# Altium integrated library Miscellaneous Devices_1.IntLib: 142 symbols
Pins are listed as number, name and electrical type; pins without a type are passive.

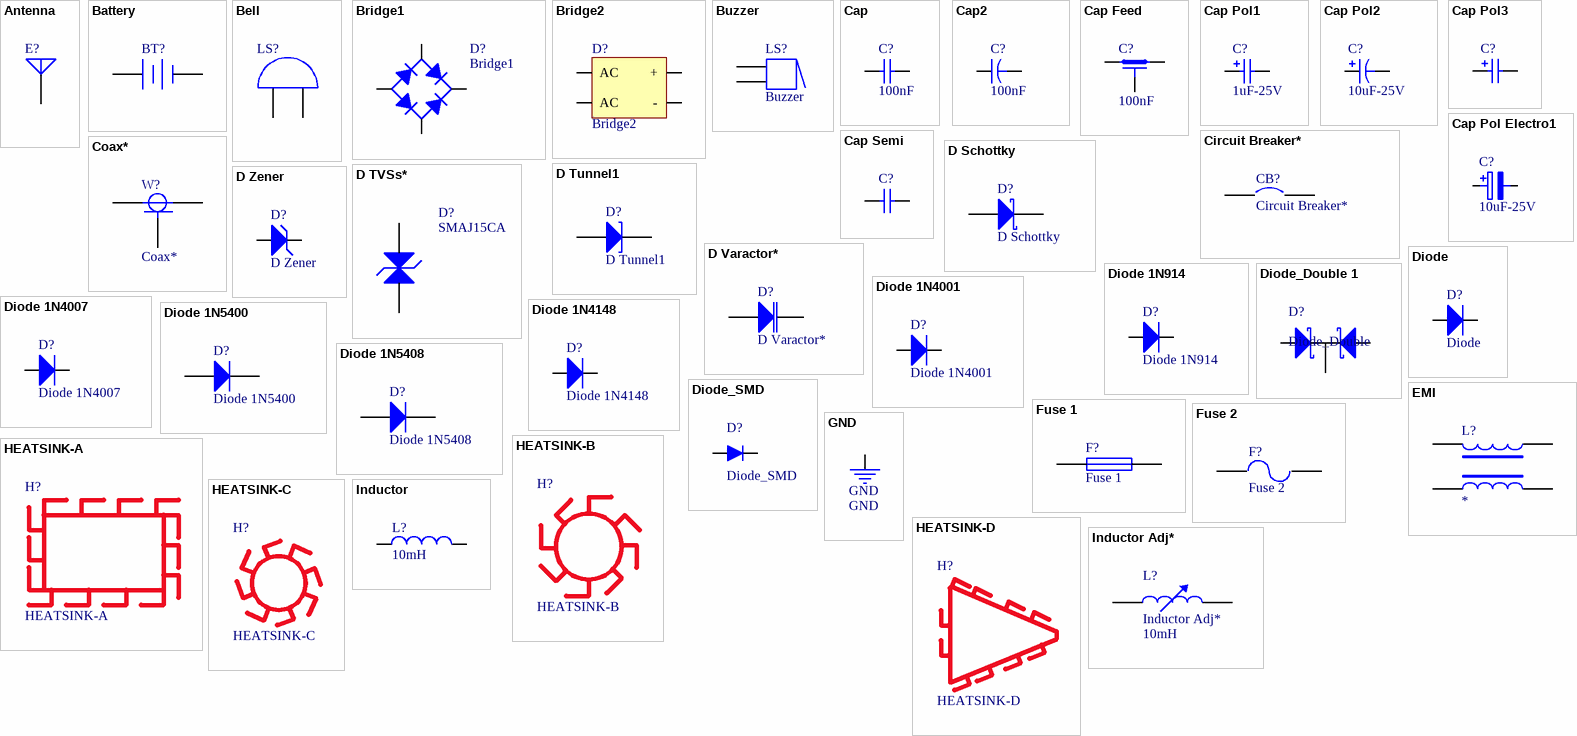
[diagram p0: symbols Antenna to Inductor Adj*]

## Antenna
designator E?
Generic Antenna
footprint PIN1 (Connector; Coax-F)
pins: 1 A

## Battery
designator BT?
Multicell Battery
footprint BAT-2 (Multicell Battery; 2 Leads)
footprint MT6CON2V
footprint MKDS3_2RMI
pins: 1 +, 2 -

## Bell
designator LS?
Electrical Bell
footprint PIN2 (Electrical Bell; 2 Leads)
pins: 1 A, 2 B

## Bridge1
designator D?
Full Wave Diode Bridge
footprint E-BIP-P4/D10 (Bridge Rectifier; 4 Terminals; Body 9.4 x 9.4 mm (typ); Pitch 5.08 mm)
simulation model BRIDGE (Spice Subcircuit)
footprint BRIDGE-1 (created by: M.Hariri (designer))
footprint BRIDGE-2
footprint BRIDGE-3
footprint BRIDGE-4
footprint BRIDGE-5
footprint BRIDGE-6
footprint BRIDGE-7
pins: 1 A, 2 C, 3 K, 4 C

## Bridge2
designator D?
Diode Bridge
footprint E-BIP-P4/X2.1 (Bridge Rectifier; 4 Terminals; Body 16.8 x 16.8 mm (typ); Pitch 10.67 mm)
simulation model BRIDGE (Spice Subcircuit)
footprint BRIDGE-1
footprint BRIDGE-2
footprint BRIDGE-3
footprint BRIDGE-4
footprint BRIDGE-5
footprint BRIDGE-6
footprint BRIDGE-7
pins: 1 -, 2 AC, 3 +, 4 AC

## Buzzer
designator LS?
Magnetic Transducer Buzzer; Revision 1: Jul-2002: Re-released for DXP Platform.; Revision 2: 17-Dec-2003: Schematic revised, PCB Footprint replaced.
footprint ABSM-1574 (Magnetic Transducer Buzzer)
footprint BUZZER
pins: 1, 1A, 2, 2A
1 alternate drawing of the same symbol

## Cap
designator C?, comment 100nF
Capacitor; Value: 100pF
footprint RAD-0.3 (Capacitor; 2 Leads)
simulation model CAP (Capacitor)
signal-integrity model Cap
footprint CAPR5.08-7.8X3.2
footprint CAPR2.54-5.1X3.2
footprint RAD0.1
footprint RAD0.15
footprint RAD0.2
footprint RAD0.2II
footprint RAD0.2III
footprint RAD0.3
footprint RAD0.3II
footprint RAD0.4
footprint RAD0.4II
footprint RAD0.6
footprint RAD0.6II
footprint RAD1.25
pins: 1, 2

## Cap2
designator C?, comment 100nF
Capacitor; Value: 100pF
footprint CAPR5-4X5 (Capacitor; 2 Leads)
simulation model CAP (Capacitor)
signal-integrity model Cap
footprint RAD0.1
footprint RAD0.2
footprint RAD0.2II
pins: 1, 2

## Cap Feed
designator C?, comment 100nF
Feed-Through Capacitor; Note: Commonly used for bypassing high-frequency currents to chassis; Value: 100pF
footprint SIP3
signal-integrity model Cap Feed
pins: 1, 2, 3

## Cap Pol1
designator C?, comment 1uF-25V
Polarized Capacitor (Radial); Value: 100pF
footprint RB7.6-15
simulation model CAP (Capacitor)
signal-integrity model Cap Pol
footprint CAPPR1.5-4X5
footprint CAPPR1.27-1.96X4.06
footprint CAPPR2-5X6.8
footprint CAPPR5-5X5
footprint CAPPR7.5-16X35
footprint RB.1/.2
footprint RB.2/.3
footprint RB.2/.3II
footprint RB.2/.4
footprint RB.3/.6
footprint RB.3/.64
footprint RB.4/.8
footprint RB.4/1.0
footprint RB.47/1.0
footprint RB.47/1.2
footprint RB.5/1.0
footprint RB1.4/.4
footprint RB1.6/.9
footprint RB.3/.6HI
footprint RB.3/.6HII
pins: 1, 2

## Cap Pol2
designator C?, comment 10uF-25V
Polarized Capacitor (Axial); Value: 100pF
footprint POLAR0.8 (Polarized Capacitor (Axial); 2 Leads)
simulation model CAP (Capacitor)
signal-integrity model Cap Pol
footprint CAPPA14.05-10.5x6.3
footprint CAPPA23.6-18.5x8.5
footprint CAPPA31.6-26.5x12.5
footprint CAPPA35.6-30.5x18.5
footprint CAPPA46.1-41x21.5
footprint RB3/6
footprint RB5/10
pins: 1, 2

## Cap Pol3
designator C?, comment 1uF-10V  (value not drawn)
Polarized Capacitor (Surface Mount)
footprint CC2012-0805 (Chip Capacitor; Body 2.0 x 1.2 mm (LxW typ))
simulation model CAP (Capacitor)
signal-integrity model Cap Pol
footprint CC4532-1812
footprint CC4564-1825
footprint CC5750-2220
footprint CC5664-2225
footprint CC3216-1206
footprint CC3225-1210
pins: 1, 2

## Cap Pol Electro1
designator C?, comment 10uF-25V
Polarized Capacitor (Radial); Value: 100pF
footprint RB7.6-15 (Polarized Capacitor (Radial); 2 Leads)
simulation model CAP (Capacitor)
signal-integrity model Cap Pol
footprint CAPPR1.5-4X5
footprint CAPPR1.27-1.96X4.06
footprint CAPPR2-5X6.8
footprint CAPPR5-5X5
footprint CAPPR7.5-16X35
footprint RB.1/.2
footprint RB.2/.3
footprint RB.2/.3II
footprint RB.2/.4
footprint RB.3/.6
footprint RB.3/.64
footprint RB.4/.8
footprint RB.4/1.0
footprint RB.47/1.0
footprint RB.47/1.2
footprint RB.5/1.0
footprint RB1.4/.4
footprint RB1.6/.9
footprint RB.3/.6HI
footprint RB.3/.6HII
footprint RB.2/.8
pins: 1, 2

## Cap Semi
designator C?, comment 100nF  (value not drawn)
Capacitor (Semiconductor SIM Model)
footprint CC3216-1206 (Chip Capacitor; Body 3.2 x 1.6 mm (LxW typ))
simulation model CAP (Semiconductor Capacitor)
signal-integrity model Cap Semi
footprint CC1310-0504
footprint CC1608-0603
footprint CC1005-0402
footprint CC3225-1210
pins: 1, 2

## Circuit Breaker*
designator CB?
Circuit Breaker
footprint SPST-2 (Circuit Breaker; 2 Leads)
pins: 1, 2

## Coax*
designator W?
Coaxial
pins: 1 CENTER 1, 2 CENTER 2, 3 SHIELD

## D Schottky
designator D?
Schottky Diode; Code - JEDEC: DO-214-AA
footprint DSO-C2/X2.3 (DO-214-AA/SMB; 2 C-Bend Leads; Body 5.3 x 3.6 mm, inc. leads (LxW))
simulation model SKYDIODE (Diode)
signal-integrity model D Schottky
footprint DIODE0.4
pins: 1 A, 2 K

## D Tunnel1
designator D?
Tunnel Diode - RLC Model; Revision 1: 15-Apr-2002: Text note added.; Revision 2: July-2002: Re-released for DXP Platform.
footprint DSO-F2/D6.1 (SMT LED; 2 Flat Leads)
simulation model DTUNNEL1 (Spice Subcircuit)
signal-integrity model D Tunnel
footprint DIODE0.4III
pins: 1 A, 2 K

## D TVSs*
designator D?, comment SMAJ15CA
400W SURFACE MOUNT TRANSIENT VOLTAGE  SUPPRESSOR
footprint SMA (Footprint not found)
pins: 1 A1, 2 A2

## D Varactor*
designator D?
Variable Capacitance Diode; Note: Pin 2 is not connected and not drawn; Code - JEDEC: SOT23
footprint SO-G3/Z3.3 (SOT-23; 3 Leads; Body 3.0 x 2.5 mm, inc. leads (LxW max))
simulation model BBY31 (Diode)
signal-integrity model D Varactor
pins: 1 K, 3 A

## D Zener
designator D?
Zener Diode
footprint DIODE-0.7 (Zener Diode; 2 Leads)
simulation model ZENER (Diode)
signal-integrity model D Zener
footprint DIODE0.4
footprint DIODE0.4II
footprint DIODE0.4II
footprint DIODE0.4IV
footprint DIODE0.45
footprint DIODE0.5
footprint DIODE0.5II
footprint DIODE0.6
footprint DIODE0.7
pins: A, K
1 alternate drawing of the same symbol

## Diode
designator D?
Default Diode; Code - JEDEC: DO-214-AB
footprint DSO-C2/X3.3 (DO-214-AB/SMC; 2 C-Bend Leads; Body 7.9 x 5.9 mm, inc. leads (LxW))
simulation model DIODE (Diode)
signal-integrity model Diode
footprint DIODE0.2
footprint DIODE0.2II
footprint DIODE0.3
footprint DIODE0.35
footprint DIODE0.4
footprint DIODE0.4III
footprint DIODE0.4II
footprint DIODE0.4IV
footprint DIODE0.5
footprint DIODE0.5II
footprint DIODE0.6
footprint DIODE0.7
footprint DIODE0.8
footprint DIODE0.8II
footprint DIODE0.7V
pins: A, K

## Diode 1N914
designator D?
High Conductance Fast Diode; Revision 1: 11-Jul-2000: SIM Model Added.; Revision 2: 17-Jul-2002: Re-released for DXP Platform.; Code - JEDEC: DO-204-AH
footprint DIO7.1-3.9x1.9 (Diode, Axial; Body 3.8 x 1.9 mm (LxDia. max), Lead Dia. 0.53 mm (max))
simulation model 1N914 (DIODE)
signal-integrity model 1N914
footprint DIODE0.2
footprint DIODE0.2II
footprint DIODE0.3
footprint DIODE0.35
footprint DIODE0.4
footprint DIODE0.4II
footprint DIODE0.4III
footprint DIODE0.4IV
pins: 1 A, 2 K

## Diode 1N4001
designator D?
1 Amp General Purpose Rectifier; Revision 1: 11-Jul-2000: SIM Model Added.; Revision 2: 17-Jul-2002: Re-released for DXP Platform.; Package Information: Latest Revision: Aug-1999; Code - JEDEC: DO-204-AL
footprint DIO10.46-5.3x2.8 (Diode, Axial; Body 5.2 x 2.7 mm (LxDia. max), Lead Dia. 0.86 mm (max))
simulation model 1N4001 (DIODE)
signal-integrity model 1N4001
footprint DIODE0.4
footprint DIODE0.4II
footprint DIODE0.4III
footprint DIODE0.4IV
footprint DIODE0.45
footprint DIODE0.5
footprint DIODE0.5II
footprint DIODE0.6
pins: 1 A, 2 K

## Diode 1N4007
designator D?
1 Amp General Purpose Rectifier; Revision 1: 11-Jul-2000: SIM Model Added.; Revision 2: 17-Jul-2002: Re-released for DXP Platform.; Package Information: Latest Revision: Aug-1999; Code - JEDEC: DO-204-AL
footprint DIO10.46-5.3x2.8 (Diode, Axial; Body 5.2 x 2.7 mm (LxDia. max), Lead Dia. 0.86 mm (max))
simulation model 1N4007 (DIODE)
signal-integrity model 1N4007
footprint DIODE0.4
footprint DIODE0.4II
footprint DIODE0.4III
footprint DIODE0.4IV
footprint DIODE0.5
footprint DIODE0.5II
footprint DIODE0.6
footprint DIODE0.45
pins: 1 A, 2 K

## Diode 1N4148
designator D?
High Conductance Fast Diode; Revision 1: 11-Jul-2000: SIM Model Added.; Revision 2: 17-Jul-2002: Re-released for DXP Platform.; Code - JEDEC: DO-204-AH
footprint DIO7.1-3.9x1.9 (Diode, Axial; Body 3.8 x 1.9 mm (LxDia. max), Lead Dia. 0.53 mm (max))
simulation model 1N4148 (DIODE)
signal-integrity model 1N4148
footprint DIODE0.2
footprint DIODE0.2II
footprint DIODE0.3
footprint DIODE0.35
footprint DIODE0.4
footprint DIODE0.4II
footprint DIODE0.4III
footprint DIODE0.4IV
pins: 1 A, 2 K

## Diode 1N5400
designator D?
3 Amp General Purpose Rectifier; Revision 1: 11-Jul-2000: SIM Model Added.; Revision 2: 17-Jul-2002: Re-released for DXP Platform.; Package Information: Latest Revision: Aug-1999
footprint DIO18.84-9.6x5.6 (Diode, Axial; Body 9.5 x 5.6 mm (LxDia. max), Lead Dia. 1.32 mm (max))
simulation model 1N5400 (DIODE)
signal-integrity model 1N5400
footprint DIODE0.7
footprint DIODE0.8
footprint DIODE0.8II
footprint DIODE0.7V
pins: 1 A, 2 K

## Diode 1N5408
designator D?
3 Amp Medium Power Silicon Rectifier Diode; Revision 1: 10-Jul-2000: SIM Model Added.; Revision 2: 17-Jul-2002: Re-released for DXP Platform.
footprint DIO18.84-9.6x5.6 (Diode, Axial; Body 9.5 x 5.3 mm (LxDia. max), Lead Dia. 1.32 mm (max))
simulation model 1N5408 (DIODE)
signal-integrity model 1N5408
footprint DIODE0.7
footprint DIODE0.8
footprint DIODE0.8II
footprint DIODE0.7V
pins: 1 A, 2 K

## Diode_Double 1
designator D?, comment Diode_Double
footprint TO220V
footprint TO220H
pins: 1 A, 2 K, 3 A

## Diode_SMD
designator D?
Default Diode; Code - JEDEC: DO-214-AB
simulation model DIODE (Diode)
signal-integrity model Diode
footprint MELF-D3516-1406
footprint DO-214AC(SMA) (Footprint not found)
pins: 1 A, 2 K

## EMI
designator L?
footprint EMI-A
pins: 1, 2, 3, 4
2 alternate drawings of the same symbol

## Fuse 1
designator F?
Fuse
footprint PIN-W2/E2.8 (Fuse; 2 Leads)
simulation model FUSE (Spice Subcircuit)
footprint FUSE-I
footprint FUSE-II
footprint CR3216-1206
pins: 1, 1a, 2, 2a

## Fuse 2
designator F?
Fuse
footprint PIN-W2/E2.8 (Fuse; 2 Leads)
simulation model FUSE (Spice Subcircuit)
footprint FUSE-I
footprint FUSE-II
pins: 1, 1a, 2, 2a

## GND
designator GND
footprint PAD(OCTAGONAL) (- Library created by DESIGNER(M.Hariri))
pins: 1 (power)
2 alternate drawings of the same symbol

## HEATSINK-A
designator H?
HEAT SINK_created by designer(M.Hariri)
footprint HEATSINK-1
footprint HEATSINK-2
footprint HEATSINK-3
footprint HEATSINK-4
2 alternate drawings of the same symbol

## HEATSINK-B
designator H?
HEAT SINK_created by designer(M.Hariri)
footprint HEATSINK-1
footprint HEATSINK-2
footprint HEATSINK-3
footprint HEATSINK-4
2 alternate drawings of the same symbol

## HEATSINK-C
designator H?
HEAT SINK_created by designer(M.Hariri)
2 alternate drawings of the same symbol

## HEATSINK-D
designator H?
HEAT SINK_created by designer(M.Hariri)
2 alternate drawings of the same symbol

## Inductor
designator L?, comment 10mH
Inductor
footprint C1005-0402 (Inductor; 2 Leads)
simulation model INDUCTOR (Inductor)
signal-integrity model Inductor
footprint CC4532-1812
footprint AXIAL0.4
footprint AXIAL0.5
footprint AXIAL0.6
pins: 1, 2

## Inductor Adj*
designator L?  value 10mH
Adjustable Inductor; Set Position: 0.5
footprint AXIAL-0.8 (Adjustable Inductor; 2 Leads)
simulation model INDUCTOR (Inductor)
signal-integrity model Inductor Adj
pins: 1, 2

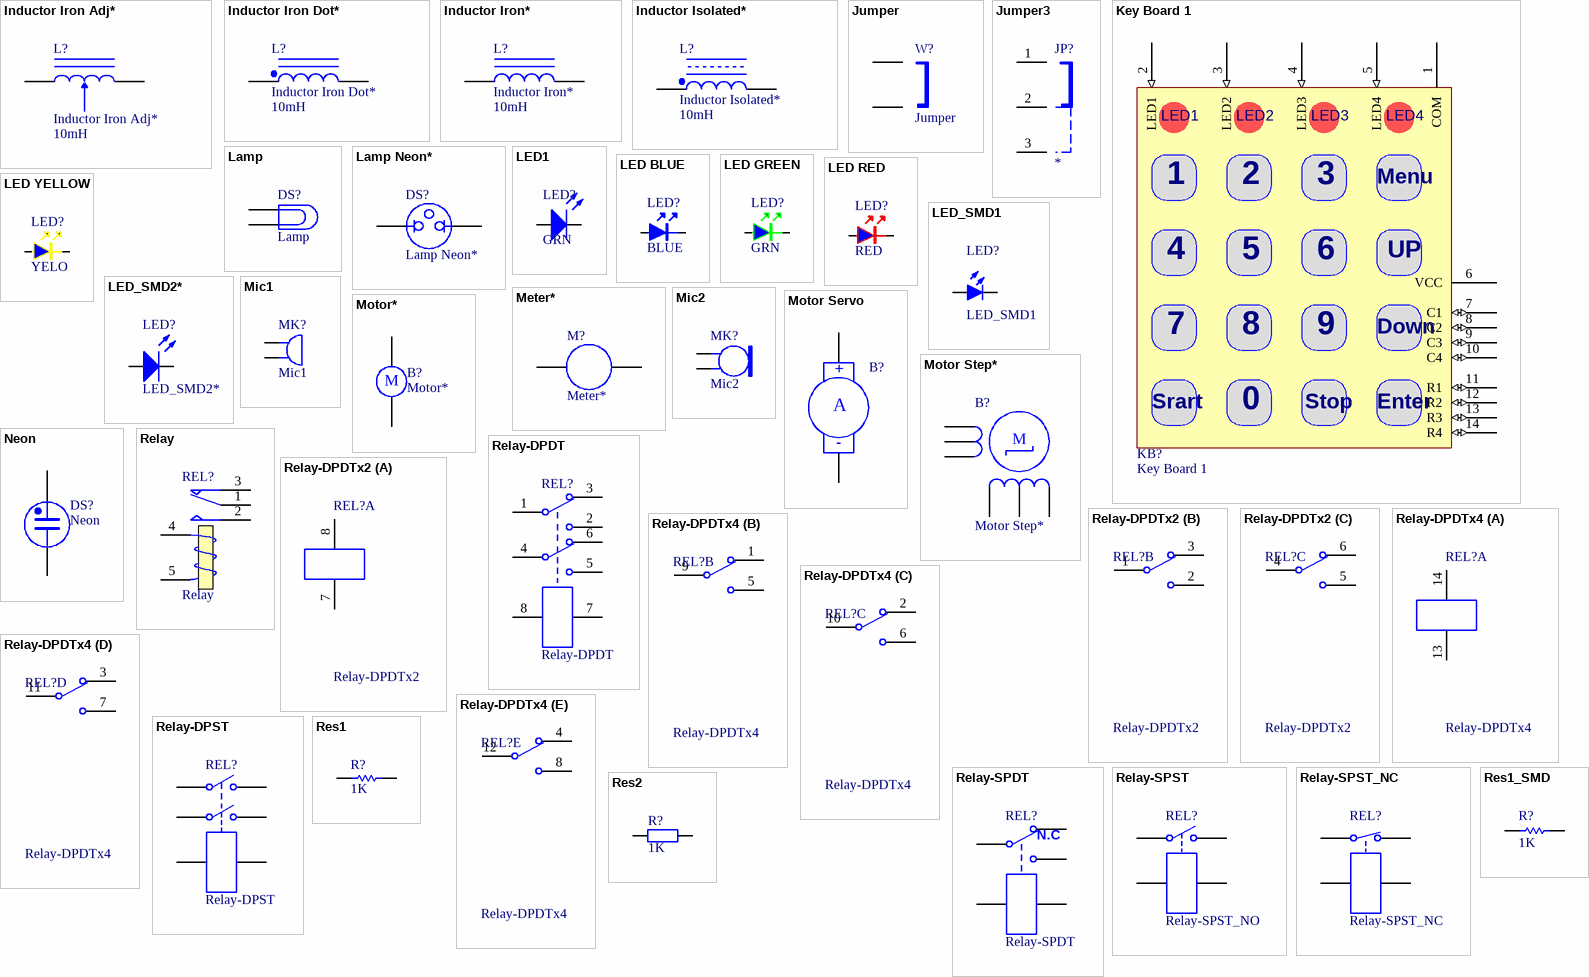
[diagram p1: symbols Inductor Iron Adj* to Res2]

## Inductor Iron Adj*
designator L?  value 10mH
Adjustable Magnetic-Core Inductor; Set Position: 0.5
footprint AXIAL-1.0 (Adjustable Magnetic-Core Inductor; 2 Leads)
simulation model INDUCTOR (Inductor)
signal-integrity model Inductor Iron Adj
pins: 1, 2

## Inductor Iron Dot*
designator L?  value 10mH
Magnetic-Core Inductor with Winding Polarity Marking
footprint DIODE SMC (Magnetic-Core Inductor with Winding Polarity Marking; 2 Leads)
signal-integrity model Inductor Iron Dot
pins: 1, 2

## Inductor Iron*
designator L?  value 10mH
Magnetic-Core Inductor
footprint AXIAL-0.9 (Magnetic-Core Inductor; 2 Leads)
simulation model INDUCTOR (Inductor)
signal-integrity model Inductor Iron
pins: 1, 2

## Inductor Isolated*
designator L?  value 10mH
Isolated Inductor
footprint SOD123/X.85 (SOD-123; 2 Leads; Body 2.7 x 1.6 mm, (LxW))
signal-integrity model Inductor Isolated
pins: 1, 2

## Jumper
designator W?
Jumper Wire
footprint RAD-0.2
footprint SIP2
footprint RAD0.2
pins: 1, 2

## Jumper3
designator JP?
Jumper
footprint SIP3
pins: 1, 2, 3
2 alternate drawings of the same symbol

## Key Board 1
designator KB?
Key Board 1_created by designer(M.Hariri)
footprint KEYBOARD01 (- Library created by DESIGNER(M.Hariri))
pins: 1 COM (power), 2 LED1 (in), 3 LED2 (in), 4 LED3 (in), 5 LED4 (in), 6 VCC (power), 7 C1 (io), 8 C2 (io), 9 C3 (io), 10 C4 (io), 11 R1 (io), 12 R2 (io), 13 R3 (io), 14 R4 (io)
2 alternate drawings of the same symbol

## Lamp
designator DS?
Incandescent Bulb
footprint PIN2 (Incandescent Bulb; 2 Leads)
footprint LAMP
footprint MT6CON2V
footprint SILFKV2S
pins: 1, 2

## Lamp Neon*
designator DS?
Neon Lamp
footprint PIN2 (Neon Lamp; 2 Leads)
pins: 1, 2

## LED1
designator LED?, comment GRN
Typical INFRARED GaAs LED
simulation model LED0 (Diode)
footprint LED-1
footprint LED-2.5MM
footprint LED-3
footprint LED-3mm
footprint LED-3.5mm
footprint LED-5mm
footprint LED-SQ
footprint SIP2-DIODE
pins: A, K

## LED BLUE
designator LED?, comment BLUE
Typical INFRARED GaAs LED
simulation model LED0 (Diode)
footprint LED-1
footprint LED-2.5MM
footprint LED-3
footprint LED-3mm
footprint LED-3.5mm
footprint LED-5mm
footprint LED-SQ
footprint SIP2-DIODE
pins: A, K

## LED GREEN
designator LED?, comment GRN
Typical INFRARED GaAs LED
simulation model LED0 (Diode)
footprint LED-1
footprint LED-2.5MM
footprint LED-3
footprint LED-3mm
footprint LED-3.5mm
footprint LED-5mm
footprint LED-SQ
footprint SIP2-DIODE
pins: A, K

## LED RED
designator LED?, comment RED
Typical INFRARED GaAs LED
simulation model LED0 (Diode)
footprint LED-1
footprint LED-2.5MM
footprint LED-3
footprint LED-3mm
footprint LED-3.5mm
footprint LED-5mm
footprint LED-SQ
footprint SIP2-DIODE
pins: A, K

## LED YELLOW
designator LED?, comment YELO
Typical INFRARED GaAs LED
simulation model LED0 (Diode)
footprint LED-1
footprint LED-2.5MM
footprint LED-3
footprint LED-3mm
footprint LED-3.5mm
footprint LED-5mm
footprint LED-SQ
footprint SIP2-DIODE
pins: A, K

## LED_SMD1
designator LED?
Typical RED, GREEN, YELLOW, AMBER GaAs LED
footprint DSO-C2/D5.6 (SM LED; 2 C-Bend Leads; Body 3.5 x 2.8 x 1.9 mm, inc leads (LxWxH typ))
simulation model LED2 (Diode)
footprint 2.0X1.25X1.1 (SM LED; 2 Flat Leads)
footprint DSO-F2/D4.4 (SM LED; 2 Flat Leads)
pins: 1 A, 2 K

## LED_SMD2*
designator LED?
Typical BLUE SiC LED; Revision 1: Jul-2002: Re-released for DXP Platform.; Revision 2: 17-Dec-2003: PCB Footprint replaced.
footprint SMD _LED (SMT LED; 2 Leads)
simulation model LED3 (Diode)
pins: 1 A, 2 K

## Meter*
designator M?
Indicating Instrument; Note: Place a "letter" into the symbol to show the function of the meter or instrument
footprint RAD-0.1 (Indicating Instrument; 2 Leads)
pins: 1, 2

## Mic1
designator MK?
Microphone
footprint PIN2 (Microphone; 2 Leads)
footprint PADx2 (- Library created by DESIGNER(M.Hariri))
footprint SIP2
pins: 1, 2

## Mic2
designator MK?
Microphone
footprint PIN2 (Microphone; 2 Leads)
footprint PADx2 (- Library created by DESIGNER(M.Hariri))
footprint SIP2
pins: 1, 2

## Motor Servo
designator B?
Servo Motor
footprint RAD-0.4 (Servo Motor; 2 Leads)
pins: 1 +, 2 -

## Motor Step*
designator B?
Motor Stepper; Code - JEDEC: MO-001-AM
footprint DIP-6 (DIP; 6 Leads; Row Spacing 7.62 mm; Pitch 2.54 mm)
pins: 1, 2, 3, 4, 5, 6

## Motor*
designator B?
Motor, General Kind
footprint RB5-10.5
pins: 1, 2

## Neon
designator DS?
Neon Bulb
footprint PIN2 (Neon Bulb; 2 Leads)
pins: 1, 2

## Relay
designator REL?
SPDT Relay
footprint DIP-P5/X1.65 (DIP; 5 Round Pins; Row Space 15.24 mm; Pitch 2.54 mm)
simulation model SPDTRELAY (Spice Subcircuit)
footprint RELAY-SPDT-1 (designer (M.Hariri))
footprint RELAY-SPDT-2
footprint RELAY-SPDT-2/2
footprint RELAY-SPDT-3
footprint RELAY-SPDT-3/2
footprint RELAY-Form C (designer (M.Hariri))
pins: 1 COM, 2 NO, 3 NC, 4 T1, 5 T2

## Relay-DPDT
designator REL?
Dual-Pole Dual-Throw Relay
footprint DIP-P8/E10 (Dual-Pole Dual-Throw Relay; 8 Leads)
simulation model DPDTRELAY (Spice Subcircuit)
footprint RELAY-DPDT-1
footprint RELAY-DPDT-2
pins: 1, 2, 3, 4, 5, 6, 7, 8

## Relay-DPDTx2
designator REL?
Dual-Pole Dual-Throw Relay_created by designer(M.Hariri)
footprint DIP-P8/E10 (Dual-Pole Dual-Throw Relay; 8 Leads)
simulation model DPDTRELAY (Spice Subcircuit)
footprint RELAY-DPDT-1
footprint RELAY-DPDT-2
part A pins: 7, 8
part B pins: 1 COM1, 2 NO1, 3 NC1
part C pins: 4 COM2, 5 NO2, 6 NC2

## Relay-DPDTx4
designator REL?
Quad Dual-Pole Dual-Throw Relay_Created by hariri.mehdi@gmail.com
simulation model DPDTRELAY (Spice Subcircuit)
footprint Relay-DPDTx4 (Footprint not found)
part A pins: 13, 14
part B pins: 1 NC1, 5 NO1, 9 COM1
part C pins: 2 NC2, 6 NO2, 10 COM2
part D pins: 3 NC3, 7 NO3, 11 COM3
part E pins: 4 NC4, 8 NO4, 12 COM4

## Relay-DPST
designator REL?
Dual-Pole Single-Throw Relay
footprint DIP-P6/D33 (DIP; 6 Round Pins; Row Space 20.32 mm; Pitch 2.54 mm)
simulation model DPSTRELAY (Spice Subcircuit)
pins: 1, 2, 4, 5, 7, 8

## Relay-SPDT
designator REL?
Single-Pole Dual-Throw Relay
footprint DIP-P5/X1.65 (DIP; 5 Round Pins; Row Space 15.24 mm; Pitch 2.54 mm)
simulation model SPDTRELAY (Spice Subcircuit)
footprint RELAY-SPDT-1
footprint RELAY-SPDT-2
footprint RELAY-SPDT-2/2
footprint RELAY-SPDT-3
footprint RELAY-SPDT-3/2
footprint RELAY-SPST-4
footprint RELAY-Form C (designer (M.Hariri))
pins: 1, 1A 1, 2, 2A 2, 3, 3A 3, 4, 5

## Relay-SPST
designator REL?, comment Relay-SPST_NO
Single-Pole Single-Throw Relay
footprint DIP-P4 (DIP; 4 Round Pins; Row Space 27.94 mm; Pitch 15.24 mm)
simulation model SPSTRELAY (Spice Subcircuit)
footprint RELAY-SPDT-2
footprint RELAY-SPDT-OEG
footprint 1 FORM B (Footprint not found)
pins: 1, 2, 4, 5

## Relay-SPST_NC
designator REL?
Single-Pole Single-Throw Relay
simulation model SPSTRELAY (Spice Subcircuit)
footprint 1 FORM A (Footprint not found)
pins: 1, 2, 4, 5

## Res1
designator R?, comment 1K
Resistor
footprint AXIAL-0.3 (Resistor; 2 Leads)
simulation model RESISTOR (Resistor)
signal-integrity model Res
footprint AXIAL0.2
footprint AXIAL0.2II
footprint AXIAL0.25
footprint AXIAL0.3
footprint AXIAL0.3II
footprint AXIAL0.4
footprint AXIAL0.4S
footprint AXIAL0.45
footprint AXIAL0.5
footprint AXIAL0.55
footprint AXIAL0.6
footprint AXIAL0.6II
footprint AXIAL0.6III
footprint AXIAL0.7
footprint AXIAL0.8
footprint AXIAL0.8II
footprint AXIAL0.9
footprint AXIAL1.0
footprint AXIAL1.2
footprint AXIAL1.4
footprint AXIAL1.5
footprint AXIAL2.0
footprint AXIAL2.125
footprint AXIAL1.0V
footprint AXIAL1.2+HeatSink (10W)
pins: 1, 2
1 alternate drawing of the same symbol

## Res1_SMD
designator R?, comment 1K
SMD Resistor
footprint C1608-0603 (Resistor; 2 Leads)
simulation model RESISTOR (Resistor)
signal-integrity model Res
footprint CR3225-1210
footprint CR5025-2010
footprint CR6332-2512
footprint CR2012-0805
pins: 1, 2
1 alternate drawing of the same symbol

## Res2
designator R?, comment 1K
Resistor
footprint AXIAL-0.3 (Resistor; 2 Leads)
simulation model RESISTOR (Resistor)
signal-integrity model Res
footprint AXIAL0.2
footprint AXIAL0.2II
footprint AXIAL0.25
footprint AXIAL0.3
footprint AXIAL0.3II
footprint AXIAL0.4
footprint AXIAL0.4S
footprint AXIAL0.45
footprint AXIAL0.5
footprint AXIAL0.55
footprint AXIAL0.6
footprint AXIAL0.6II
footprint AXIAL0.6III
footprint AXIAL0.7
footprint AXIAL0.8
footprint AXIAL0.8II
footprint AXIAL0.9
footprint AXIAL1.0
footprint AXIAL1.2
footprint AXIAL1.4
footprint AXIAL1.5
footprint AXIAL2.0
footprint AXIAL2.125
footprint AXIAL1.2+HeatSink (10W)
pins: 1, 2
1 alternate drawing of the same symbol

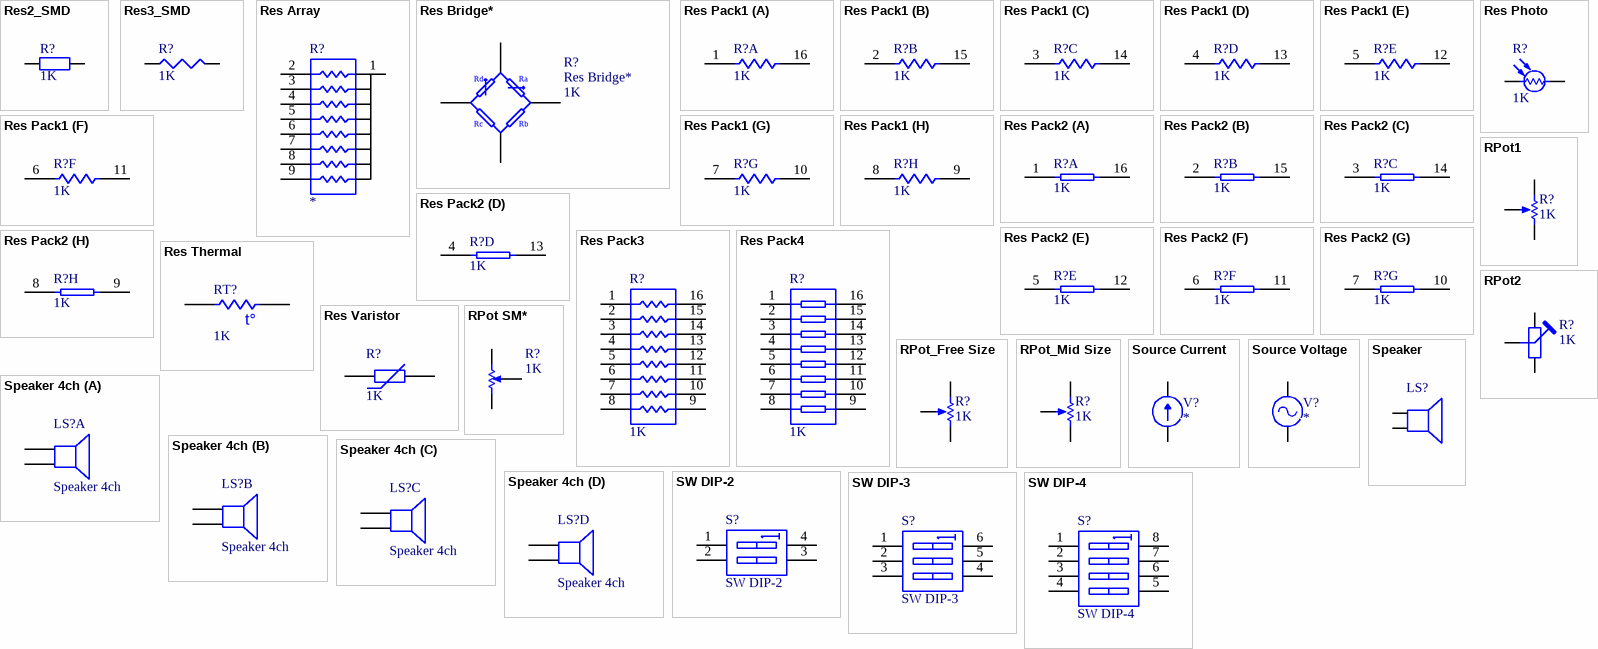
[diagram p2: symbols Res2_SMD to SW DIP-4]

## Res2_SMD
designator R?, comment 1K
SMD Resistor
simulation model RES (Semiconductor Resistor)
signal-integrity model Res Semi
footprint CR1005-0402
footprint CR1608-0603
footprint CR2012-0805
footprint CR3216-1206
pins: 1, 2
1 alternate drawing of the same symbol

## Res3_SMD
designator R?, comment 1K
SMD Resistor
footprint C1608-0603 (Resistor; 2 Leads)
simulation model RESISTOR (Resistor)
signal-integrity model Res
footprint CR3225-1210
footprint CR5025-2010
footprint CR6332-2512
pins: 1, 2
1 alternate drawing of the same symbol

## Res Array
designator R?
Resistor Array
footprint SIP9
pins: 1, 2, 3, 4, 5, 6, 7, 8, 9

## Res Bridge*
designator R?  value 1K
Resistor Bridge
footprint SFM-T4/A4.1V (TO, Thru-Hole, Vertical, Heatsink Mounted; 4 In-Line Leads; Pitch 2.54 mm)
signal-integrity model Res Bridge
footprint SILFKV4S
pins: 1, 2, 3, 4

## Res Pack1
designator R?, comment 1K
Resistor Array - Parts; Code - JEDEC: MS-012-AC; Code - IPC: SO16
footprint SO-G16 (Small Outline; 16 Leads; Body Width 3.9 mm; Pitch 1.27 mm)
simulation model RESISTOR (Resistor)
signal-integrity model Res Pack
footprint DIP16E
part A pins: 1, 16
part B pins: 2, 15
part C pins: 3, 14
part D pins: 4, 13
part E pins: 5, 12
part F pins: 6, 11
part G pins: 7, 10
part H pins: 8, 9

## Res Pack2
designator R?, comment 1K
Resistor Array - Parts; Code - JEDEC: MO-001-AC
footprint DIP-16 (DIP; 16 Leads; Row Spacing 7.62 mm; Pitch 2.54 mm)
simulation model RESISTOR (Resistor)
signal-integrity model Res Pack
footprint DIP16E
part A pins: 1, 16
part B pins: 2, 15
part C pins: 3, 14
part D pins: 4, 13
part E pins: 5, 12
part F pins: 6, 11
part G pins: 7, 10
part H pins: 8, 9

## Res Pack3
designator R?, comment 1K
Isolated Resistor Network
footprint SO-G16/Z8.5 (Small Outline; 16 Leads; Body Width 5.6 mm; Pitch 1.27 mm)
simulation model respack_8 (Spice Subcircuit)
footprint DIP16E
pins: 1, 2, 3, 4, 5, 6, 7, 8, 9, 10, 11, 12, 13, 14, 15, 16

## Res Pack4
designator R?, comment 1K
Resistor Array; Code - JEDEC: MO-150-AC
footprint SSO-G16/X.4 (SSOP; 16 Leads; Body Width 5.3 mm; Pitch 0.65 mm)
simulation model respack_8 (Spice Subcircuit)
footprint DIP16E
pins: 1, 2, 3, 4, 5, 6, 7, 8, 9, 10, 11, 12, 13, 14, 15, 16

## Res Photo
designator R?, comment 1K
Photosensitive Resistor
footprint PIN2 (Photosensitive Diode; 2 Leads)
pins: 1, 2

## Res Thermal
designator RT?, comment 1K
Thermistor
footprint R2012-0805 (Thermistor; 2 Leads)
footprint AXIAL0.4
pins: 1, 2
1 alternate drawing of the same symbol

## Res Varistor
designator R?, comment 1K
Varistor (Voltage-Sensitive Resistor)
footprint R2012-0805 (Varistor (Voltage-Sensitive Resistor); 2 Leads)
footprint AXIAL0.4
pins: 1, 2

## RPot1
designator R?, comment 1K
Potentiometer; Set Position: 0.5
footprint VR5
simulation model POT (Potentiometer)
footprint VR2
footprint VR1
footprint VR3
footprint VR4
footprint VR6-4.9/10.6MM
footprint VR7-10/17.7MM
footprint VR8-5/5.6MM
footprint VOL-B_on board
footprint VOL-A
footprint VOL-C
footprint VOL-E
pins: 1 TOP, 1a TOP, 2 BOT, 2a BOT, 3 TAP
1 alternate drawing of the same symbol

## RPot2
designator R?, comment 1K
Potentiometer; Set Position: 0.5
footprint VR5
simulation model POT (Potentiometer)
footprint VR2
footprint VR1
footprint VR3
footprint VR4
footprint VR6-4.9/10.6MM
footprint VR7-10/17.7MM
footprint VR8-5/5.6MM
footprint VOL-B_on board
footprint VOL-A
footprint VOL-C
footprint VOL-E
pins: 1 TOP, 1a TOP, 2 BOT, 2a BOT, 3 TAP
1 alternate drawing of the same symbol

## RPot SM*
designator R?, comment 1K
Square Trimming Potentiometer
footprint POT4MM-2 (Square Trimming Potentiometer)
pins: CCW -, CW +, W
1 alternate drawing of the same symbol

## RPot_Free Size
designator R?, comment 1K
Potentiometer_created by designer(M.Hariri); Set Position: 0.5
footprint VR_FREE SIZE
simulation model POT (Potentiometer)
pins: 1 TOP, 1a TOP, 2 BOT, 2a BOT, 3 TAP, 3a TAP, 3b TAP, 3c TAP
1 alternate drawing of the same symbol

## RPot_Mid Size
designator R?, comment 1K
Potentiometer_created by designer(M.Hariri); Set Position: 0.5
footprint VR_MID SIZE
simulation model POT (Potentiometer)
pins: 1 TOP, 1a TOP, 2 BOT, 2a BOT, 3 TAP, 3a TAP
1 alternate drawing of the same symbol

## Source Current
designator V?
footprint MT6CON2V
pins: 1, 2
2 alternate drawings of the same symbol

## Source Voltage
designator V?
footprint MT6CON2V
pins: 1, 2
2 alternate drawings of the same symbol

## Speaker
designator LS?
Loudspeaker
footprint PIN2 (Loudspeaker; 2 Leads)
footprint SIP2
footprint PADx2 (- Library created by DESIGNER(M.Hariri))
pins: 1, 2

## Speaker 4ch
designator LS?
Loudspeaker 4 Channel_created by designer(M.Hariri)
footprint SP_4-channel (- Library created by DESIGNER(M.Hariri))
part A pins: 1, 2
part B pins: 3, 4
part C pins: 5, 6
part D pins: 7, 8

## SW DIP-2
designator S?
DIP Switch
footprint DIP-4 (DIP; 4 Leads; Row Spacing 7.62 mm; Pitch 2.54 mm)
simulation model dpsw2 (Spice Subcircuit)
footprint DIP4E
pins: 1 A1, 2 A2, 3 B2, 4 B1

## SW DIP-3
designator S?
DIP Switch; Code - JEDEC: MO-001-AM
footprint DIP-6 (DIP; 6 Leads; Row Spacing 7.62 mm; Pitch 2.54 mm)
simulation model dpsw3 (Spice Subcircuit)
footprint DIP6E
pins: 1 A1, 2 A2, 3 A3, 4 B3, 5 B2, 6 B1

## SW DIP-4
designator S?
DIP Switch; Code - JEDEC: MS-012-AA; Code - IPC: SO8
footprint SO-G8 (Small Outline; 8 Leads; Body Width 3.9 mm; Pitch 1.27 mm)
simulation model dpsw4 (Spice Subcircuit)
footprint DIP8E
pins: 1 A1, 2 A2, 3 A3, 4 A4, 5 B4, 6 B3, 7 B2, 8 B1

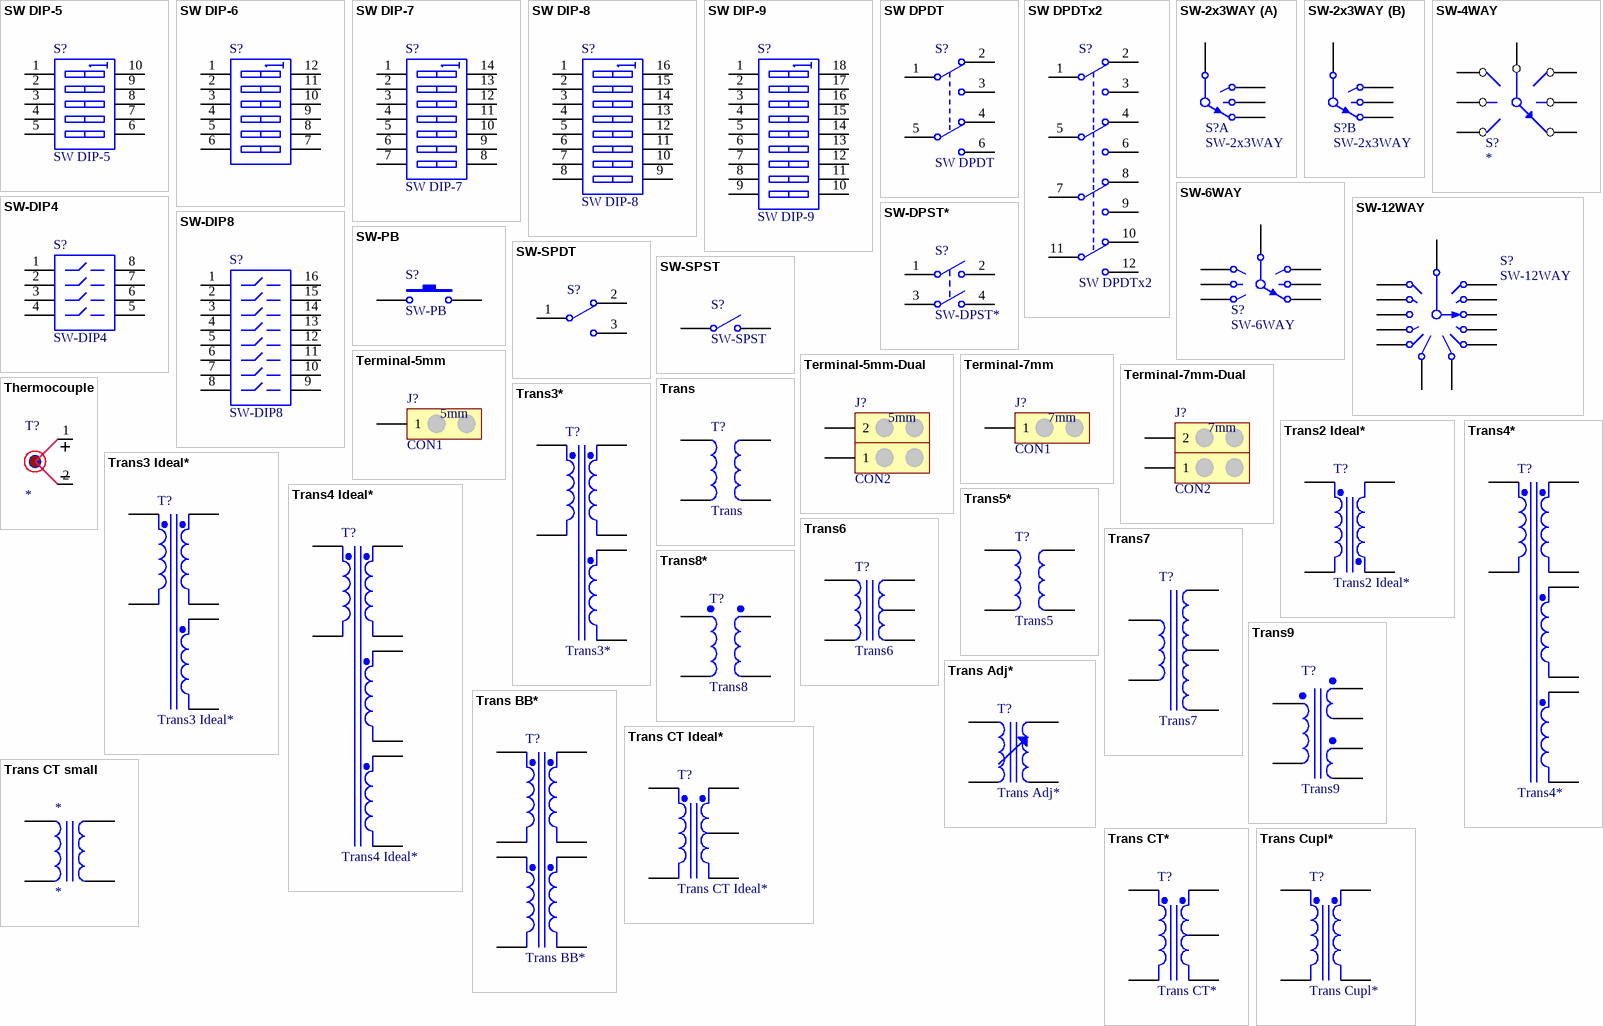
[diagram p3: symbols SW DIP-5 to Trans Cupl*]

## SW DIP-5
designator S?
DIP Switch
footprint DIP-10/D14.5
simulation model dpsw5 (Spice Subcircuit)
pins: 1 A1, 2 A2, 3 A3, 4 A4, 5 A5, 6 B5, 7 B4, 8 B3, 9 B2, 10 B1

## SW DIP-6
designator S?
DIP Switch
footprint DIP-12/SW (DIP Switch; 12 Leads)
simulation model dpsw6 (Spice Subcircuit)
pins: 1 A1, 2 A2, 3 A3, 4 A4, 5 A5, 6 A6, 7 B6, 8 B5, 9 B4, 10 B3, 11 B2, 12 B1

## SW DIP-7
designator S?
DIP Switch; Code - JEDEC: MO-001-AF
footprint DIP-14 (DIP; 14 Leads; Row Spacing 7.62 mm; Pitch 2.54 mm)
simulation model dpsw7 (Spice Subcircuit)
footprint DIP14E
pins: 1 A1, 2 A2, 3 A3, 4 A4, 5 A5, 6 A6, 7 A7, 8 B7, 9 B6, 10 B5, 11 B4, 12 B3, 13 B2, 14 B1

## SW DIP-8
designator S?
DIP Switch
footprint DIP_SW_8WAY_SMD (DIP Switch; 16 Leads)
simulation model dpsw8 (Spice Subcircuit)
footprint DIP16E
pins: 1 A1, 2 A2, 3 A3, 4 A4, 5 A5, 6 A6, 7 A7, 8 A8, 9 B8, 10 B7, 11 B6, 12 B5, 13 B4, 14 B3, 15 B2, 16 B1

## SW DIP-9
designator S?
DIP Switch; Code - JEDEC: MO-036-AE
footprint DIP-18 (DIP; 18 Leads; Row Spacing 7.62 mm; Pitch 2.54 mm)
simulation model dpsw9 (Spice Subcircuit)
footprint DIP18E
pins: 1 A1, 2 A2, 3 A3, 4 A4, 5 A5, 6 A6, 7 A7, 8 A8, 9 A9, 10 B9, 11 B8, 12 B7, 13 B6, 14 B5, 15 B4, 16 B3, 17 B2, 18 B1

## SW DPDT
designator S?
Double-Pole, Double-Throw Switch
footprint SO-G6/P.95 (SOT-23/SC-74A; 5 Leads; Body 3.1 x 3 mm, inc. leads (LxW max))
footprint KEY_5 (- Library created by DESIGNER(M.Hariri))
footprint KEY_6 (- Library created by DESIGNER(M.Hariri))
pins: 1 COMMON1, 2 NC1, 3 NO1, 4 NC2, 5 COMMON2, 6 NO2

## SW DPDTx2
designator S?
Switch_created by designer(M.Hariri)
footprint KEY_6X2
pins: 1 COMMON1, 2 NC1, 3 NO1, 4 NC2, 5 COMMON2, 6 NO2, 7 COMMON3, 8 NC3, 9 NO3, 10 NC4, 11 COMMON4, 12 NO4

## SW-2x3WAY
designator S?
6 Way Switch
footprint SW-2x3WAY
part A pins: 1, 3, 4, 5
part B pins: 6, 7, 8, 10

## SW-4WAY
designator S?
4 Way Switch
footprint MT6CON5V
footprint SMK5R5MIL_A
pins: 1, 2, 3, 4, 5, 6, 7
2 alternate drawings of the same symbol

## SW-6WAY
designator S?
6 Way Switch
footprint SW-7
footprint MT6CON7V
footprint SIP7
pins: 1, 2, 3, 4, 5, 6, 7

## SW-12WAY
designator S?
12 Way Switch
footprint DIP-13(14)
footprint MT6CON12V
footprint SIP12
pins: 1, 2, 3, 5, 6, 7, 8, 9, 10, 11, 12, 13, 14

## SW-DIP4
designator S?
DIP Switch
footprint DIP-8
simulation model dpsw4 (Spice Subcircuit)
footprint DIP8E
pins: 1, 2, 3, 4, 5, 6, 7, 8

## SW-DIP8
designator S?
4009 Series DIP Switch, Raised actuator; Revision 1: Jul-2002: Re-released for DXP Platform.; Revision 2: 17-Dec-2003: PCB Footprint replaced.
footprint DIP-16-KEY
simulation model dpsw8 (Spice Subcircuit)
footprint DIP16E
pins: 1, 2, 3, 4, 5, 6, 7, 8, 9, 10, 11, 12, 13, 14, 15, 16

## SW-DPST*
designator S?
Double-Pole, Single-Throw Switch
footprint DPST-4
pins: 1 COMMON1, 2 NO1, 3 COMMON2, 4 NO2

## SW-PB
designator S?
PUSH BUTTON
footprint SPST-2
footprint KEY_1
footprint MICROSWITCH (- Library created by DESIGNER(M.Hariri))
footprint MICROSWITCH-II (- Library created by DESIGNER(M.Hariri))
footprint PUSH BOTTOM (- Library created by DESIGNER(M.Hariri))
pins: 1, 1a 1, 2, 2a 2

## SW-SPDT
designator S?
SPDT Subminiature Toggle Switch, Right Angle Mounting, Vertical Actuation; Revision 1: Jul-2002: Re-released for DXP Platform.; Revision 2: 17-Dec-2003: Schematic revised, PCB Footprint replaced.
footprint TL36WW15050
footprint MT6CON3V
footprint SILFKV3S
pins: 1, 2, 3

## SW-SPST
designator S?
Single-Pole, Single-Throw Switch
footprint SPST-2
footprint MICROSWITCH (- Library created by DESIGNER(M.Hariri))
footprint PADx2 (- Library created by DESIGNER(M.Hariri))
footprint PUSH BUTTON (Footprint not found)
footprint SIP2
pins: 1 COMMON, 1a COMMON, 2 NO, 2a NO

## Terminal-5mm
designator J?, comment CON1
Connector - Library created by DESIGNER(M.Hariri)
footprint Terminal-5mm (- Library created by DESIGNER(M.Hariri))
pins: 1, 1A, 1B

## Terminal-5mm-Dual
designator J?, comment CON2
Connector - Library created by DESIGNER(M.Hariri)
footprint Terminal-5mm-Dual (- Library created by DESIGNER(M.Hariri))
pins: 1, 1A, 1B, 2, 2A, 2B

## Terminal-7mm
designator J?, comment CON1
Connector - Library created by DESIGNER(M.Hariri)
footprint Terminal-7mm (- Library created by DESIGNER(M.Hariri))
pins: 1, 1A, 1B

## Terminal-7mm-Dual
designator J?, comment CON2
Connector - Library created by DESIGNER(M.Hariri)
footprint Terminal-7mm-Dual (- Library created by DESIGNER(M.Hariri))
pins: 1, 1A, 1B, 2, 2A, 2B

## Thermocouple
designator T?
Thermocouple
footprint SIP2
footprint PAD*2
footprint SMK2R5MIL_A
footprint Terminal-5mm-Dual (- Library created by DESIGNER(M.Hariri))
footprint Terminal-7mm-Dual (- Library created by DESIGNER(M.Hariri))
pins: 1, 1a 1, 1b 1, 2, 2a 2, 2b 2
2 alternate drawings of the same symbol

## Trans
designator T?
Transformer
footprint TRANS (Transformer; 4 Leads)
simulation model TRANSFORMER (Transformer)
footprint Trans-01
pins: 1, 2, 3, 4

## Trans2 Ideal*
designator T?
Transformer (Ideal)
footprint TRF_4 (Transformer (Ideal); 4 Leads)
footprint Trans-01
pins: 1 Pri+, 2 Pri-, 3 Sec+, 4 Sec-

## Trans3 Ideal*
designator T?
Three-winding Transformer (Ideal)
footprint TRF_6 (Three-winding Transformer (Ideal); 6 Leads)
simulation model IDEAL3W (Spice Subcircuit)
pins: 1 Pri+, 2 Pri-, 3 Sec1+, 4 Sec1-, 5 Sec2+, 6 Sec2-

## Trans3*
designator T?
Three-winding Transformer (Non-Ideal)
footprint TRF_6 (Three-winding Transformer (Non-Ideal); 6 Leads)
simulation model NI3WTRANS (Spice Subcircuit)
pins: 1 Pri+, 2 Pri-, 3 Sec1+, 4 Sec1-, 5 Sec2+, 6 Sec2-

## Trans4 Ideal*
designator T?
Four-winding Transformer (Ideal)
footprint TRF_8
simulation model IDEAL4W (Spice Subcircuit)
pins: 1 Pri+, 2 Pri-, 3 Sec1+, 4 Sec1-, 5 Sec2+, 6 Sec2-, 7 Sec3+, 8 Sec3-

## Trans4*
designator T?
Four-winding Transformer (Non-Ideal)
footprint TRF_8 (Four-winding Transformer (Non-Ideal); 8 Leads)
simulation model NI4WTRANS (Spice Subcircuit)
pins: 1 Pri+, 2 Pri-, 3 Sec1+, 4 Sec1-, 5 Sec2+, 6 Sec2-, 7 Sec3+, 8 Sec3-

## Trans5*
designator T?, comment Trans5
footprint TRF_EI30_1
pins: 1, 5, 7, 9

## Trans6
designator T?
footprint TRF_E51-40_62_2
footprint TRF_EI38_2
pins: 1, 5, 7, 8, 9

## Trans7
designator T?
footprint TRF_E51-40_62_2
footprint TRF_EI38_2
pins: 1, 5, 7, 8, 9

## Trans8*
designator T?, comment Trans8
pins: 1, 2, 3, 4

## Trans9
designator T?
footprint TRF_EI30_2
pins: 1, 5, 6, 7, 9, 10

## Trans Adj*
designator T?
Variable Transformer
footprint TRF_4 (Variable Transformer; 4 Leads)
simulation model TRANSFORMER (Transformer)
pins: 1, 2, 3, 4

## Trans BB*
designator T?
Buck-boost Transformer (Ideal)
footprint TRF_8 (Buck-boost Transformer (Ideal); 8 Leads)
simulation model IDEAL4W (Spice Subcircuit)
pins: 1 Pri1+, 2 Pri1-, 3 Pri2+, 4 Pri2-, 5 Sec1+, 6 Sec1-, 7 Sec2+, 8 Sec2-

## Trans CT Ideal*
designator T?
Center-Tapped Transformer (Ideal)
footprint TRF_5 (Center-Tapped Transformer (Ideal); 5 Leads)
simulation model IDEALTRANSCT (Spice Subcircuit)
pins: 1 Pri+, 2 Pri-, 3 Sec+, 4 SecCT, 5 Sec-

## Trans CT small
designator *
footprint CT-01
footprint CT-02
pins: 1, 2, 3, 4

## Trans CT*
designator T?
Center-Tapped Transformer (Coupled Inductor Model)
footprint TRF_5 (Center-Tapped Transformer (Coupled Inductor Model); 5 Leads)
simulation model TRANSFORMER (Transformer)
pins: 1 Pri+, 2 Pri-, 3 Sec+, 4 SecCT, 5 Sec-

## Trans Cupl*
designator T?
Transformer (Coupled Inductor Model)
footprint TRF_4 (Transformer (Coupled Inductor Model); 4 Leads)
simulation model TRANSFORMER (Transformer)
pins: 1 Pri+, 2 Pri-, 3 Sec+, 4 Sec-

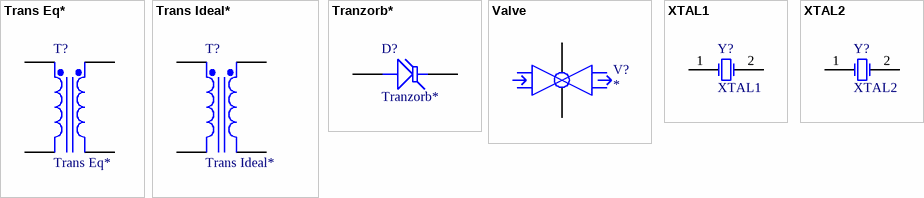
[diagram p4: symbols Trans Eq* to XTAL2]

## Trans Eq*
designator T?
Transformer (Equivalent Circuit Model)
footprint TRF_4 (Transformer (Equivalent Circuit Model); 4 Leads)
simulation model TRANS (Spice Subcircuit)
pins: 1 Pri+, 2 Pri-, 3 Sec+, 4 Sec-

## Trans Ideal*
designator T?
Transformer (Ideal)
footprint TRF_4 (Transformer (Ideal); 4 Leads)
simulation model IDEALTRANS (Spice Subcircuit)
pins: 1 Pri+, 2 Pri-, 3 Sec+, 4 Sec-

## Tranzorb*
designator D?
Tranzorb
footprint DIO10.2-7X2.7 (Diode, Axial; Body 7 x 2.7 mm (LxDia. max), Lead Dia. 0.53 mm (max))
pins: 1 A, 2 K

## Valve
designator V?
Electrical Valve_created by designer(M.Hariri)
footprint MT6CON2V
footprint SILFKV2S
pins: 1, 2
2 alternate drawings of the same symbol

## XTAL1
designator Y?
Crystal Oscillator
simulation model XTAL (Spice Subcircuit)
footprint XTAL1
pins: 1 OSC1, 2 OSC2

## XTAL2
designator Y?
Crystal Oscillator
footprint BCY-W2/D3.1
simulation model XTAL (Spice Subcircuit)
pins: 1 OSC1, 2 OSC2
